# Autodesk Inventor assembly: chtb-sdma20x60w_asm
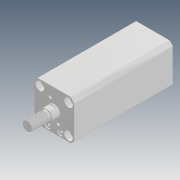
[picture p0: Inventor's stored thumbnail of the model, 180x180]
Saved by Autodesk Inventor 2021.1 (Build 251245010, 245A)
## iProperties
Company: Microsoft
Created: 2018-05
Part Number: chtb-sdma20x60w_asm
Description: STEP AP214
Document SubType Name: Assembly
Designer: user
Title: chtb-sdma20x60w_asm.STEP
Author: Windows
Revision Number: ÈÎºÎ
Sending System: SolidWorks 2015
Preprocessor: SwSTEP 2.0
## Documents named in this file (4)
- D:\Vault_2016\Projekty\Clamptek\Hydraulic\CHTB\CHTB-20\Inventor\CHTB-SDMA20x60W\chtb-sdma20x60w_asm.iam
- D:\Vault_2016\Projekty\Clamptek\Hydraulic\CHTB\CHTB-20\Inventor\CHTB-SDMA20x60W\CHTB-SDMA20X60NBT.ipt
- D:\Vault_2016\Projekty\Clamptek\Hydraulic\CHTB\CHTB-20\Inventor\CHTB-SDMA20x60W\CHTB-SDMA20X60WHSG.ipt
- D:\Vault_2016\Projekty\Clamptek\Hydraulic\CHTB\CHTB-20\Inventor\CHTB-SDMA20x60W\QG_3.ipt
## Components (3 placed, 3 different names)
1. CHTB-SDMA20X60NBT_1
2. CHTB-SDMA20X60WHSG_2
3. QG_3_3
